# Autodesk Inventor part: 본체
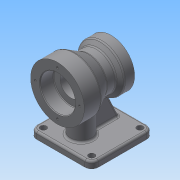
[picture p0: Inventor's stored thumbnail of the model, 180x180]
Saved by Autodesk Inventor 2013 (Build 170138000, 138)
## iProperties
Created: 2019-01
Part Number: 본체
Material: 일반
Document SubType Name: Modeling
Designer: Administrator
Density: 1 g/cm^3
Author: Administrator
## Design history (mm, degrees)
sketch "스케치2"
  geometry: L1 (-35, 0)-(-35, 40); L2 (-35, 40)-(-10, 40); L3 (-10, 40)-(10.785, 28); L4 (10.785, 28)-(24.126, 28); L5 (24.126, 28)-(30, 35); L6 (30, 35)-(45, 35); L7 (45, 35)-(45, 0); L8 (45, 0)-(-35, 0); 1 further point
  constraints: 16 end point, 2 parallel, 2 perpendicular, 2 vertical, 1 point on line
  dimensions: "d1" = 80 diameter of L2 L8; "d3" = 70 diameter of L6 L8; "d5" = 50 deg angle of L4 L5; "d6" = 30 deg angle of L4 L3; "d7" = 15 distance of L5.end L6.end; "d8" = 25 distance of L1.end L2.end; "d9" = 80 distance of L7.end L1.start; "d10" = 56 diameter of L4 L8; "d11" = 35 distance of point (0, 0) L1.start
revolve "회전1" sketch "스케치2" stored, may be unused: angle "d12" = 90 deg
node "작업 평면1"
sketch "스케치3"
  geometry: L1 (30, 46)-(-62, 46); L2 (-62, 46)-(-62, -46); L3 (-62, -46)-(30, -46); L4 (30, -46)-(30, 46); 2 further points
  constraints: 8 end point, 2 parallel, 1 horizontal, 1 horizontal alignment, 1 midpoint, 1 perpendicular
  dimensions: "d14" = 92 distance of L2.end L3.end; "d16" = 92 distance of L1.end L2.end (= d14); "d17" = 30 distance of point (30, 0) point (0, 0)
extrude "돌출1" join sketch "스케치3" distance "d18" = 10; taper "d19" = 0 deg
sketch "스케치4"
  geometry: C1 r 16 at (0, 0); 1 further point
  constraints: 1 centre point, 1 coincident
  dimensions: "d20" = 32 diameter of C1
extrude "돌출2" join sketch "스케치4" stored distance "d21" = 10; taper "d22" = 0 deg
fillet "모깎기1" dims "d24" = 10
sketch "스케치5"
  geometry: L1 (52, -70)-(-20, -70) reference; L2 (52, -70)-(62, -70) reference; L3 (0, 0)-(45, 0); L4 (45, -35)-(45, 35) reference; L5 (52, -70)-(19.358, 0)
  constraints: 4 end point, 2 point on line, 1 midpoint
  dimensions: "d25" = 10 distance of L2.end L5.start; "d27" = 65 deg angle of L1 L5
feature "리브1" sketch "스케치5" dims "d28" = 1, "d29" = 10, "d30" = 0, "d31" = 0, "d32" = 1, "d33" = 1
sketch "스케치6"
  geometry: L1 (-35, -40)-(-35, 40) reference; L2 (45, -35)-(45, 35) reference; L3 (-35, 0)-(45, 0); L4 (45, 0)-(45, 20); L5 (45, 20)-(28, 20); L6 (30, -34.641)-(30, 35) reference; L7 (28, 20)-(28, 16); L8 (28, 16)-(-15, 16); L9 (-15, 16)-(-15, 26); L10 (-15, 26)-(-35, 26); L11 (-35, 26)-(-35, 0); 1 further point
  constraints: 16 end point, 3 perpendicular, 2 midpoint, 2 parallel, 2 point on line, 1 collinear
  dimensions: "d34" = 20 distance of L9.end L10.end; "d36" = 17 distance of L4.end L5.end; "d37" = 52 diameter of L10 L3; "d38" = 32 diameter of L8 L3; "d39" = 40 diameter of L5 L3
revolve "회전2" sketch "스케치6" stored, may be unused: angle "d40" = 90 deg
fillet "모깎기2" dims "d41" = 1
fillet "모깎기3" dims "d42" = 0.6
chamfer "모따기1" distance "d43" = 1; stored, may be unused: second distance "d44" = 2, angle "d45" = 45 deg
sketch "스케치7"
  geometry: C1 r 4.5 at (52, -36); A1 r 10 centre (52, -36) between (52, -46) and (62, -36) reference
  constraints: 1 centre point, 1 coincident
  dimensions: "d46" = 9 diameter of C1
extrude "돌출3" cut sketch "스케치7" stored distance "d47" = 10; taper "d48" = 0 deg
node "작업 평면2"
sketch "스케치8" dims "d49" = 55
  geometry: C1 r 35 at (0, 0) reference; C2 r 21 at (0, 0) reference; 2 further points
  constraints: 2 vertical alignment, 1 coincident, 2 other
hole "구멍1" sketch "스케치8" at (0, 27.5) diameter "d50" = 3.242; stored, may be unused: countersink angle "d54" = 90 deg, drill point angle "d56" = 118 deg; dims "d51" = 9, "d52" = 4, "d53" = 2, "d55" = 11
sketch "스케치9" dims "d60" = 66
  geometry: C1 r 40 at (0, 0) reference; C2 r 27 at (0, 0) reference; 2 further points
  constraints: 2 vertical alignment, 1 coincident, 2 other
hole "구멍2" sketch "스케치9" at (0, 33) diameter "d61" = 3.242; stored, may be unused: countersink angle "d65" = 90 deg, drill point angle "d67" = 118 deg; dims "d62" = 9, "d63" = 4, "d64" = 2, "d66" = 11
fillet "모깎기4" dims "d71" = 3
fillet "모깎기5" dims "d72" = 3
fillet "모깎기6" dims "d73" = 3
fillet "모깎기7" dims "d74" = 3
fillet "모깎기8" dims "d75" = 3
node "솔리드1"
mirror "대칭1"
mirror "대칭2"
pattern_circular "원형 패턴1" dims angle "d58" = 360 deg
pattern_circular "원형 패턴2" dims angle "d69" = 360 deg
